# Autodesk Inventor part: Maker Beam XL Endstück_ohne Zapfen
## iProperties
Created: 2017-03
Part Number: Maker Beam XL Endstück_ohne Zapfen
Document SubType Name: Modeling
Designer: Acer
Density: 1 g/cm^3
Author: Acer
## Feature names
1. Extrusion7
2. Extrusion10
3. Rundung3 [Fillet]
4. Extrusion12
5. Extrusion14
6. Rundung7 [Fillet]
